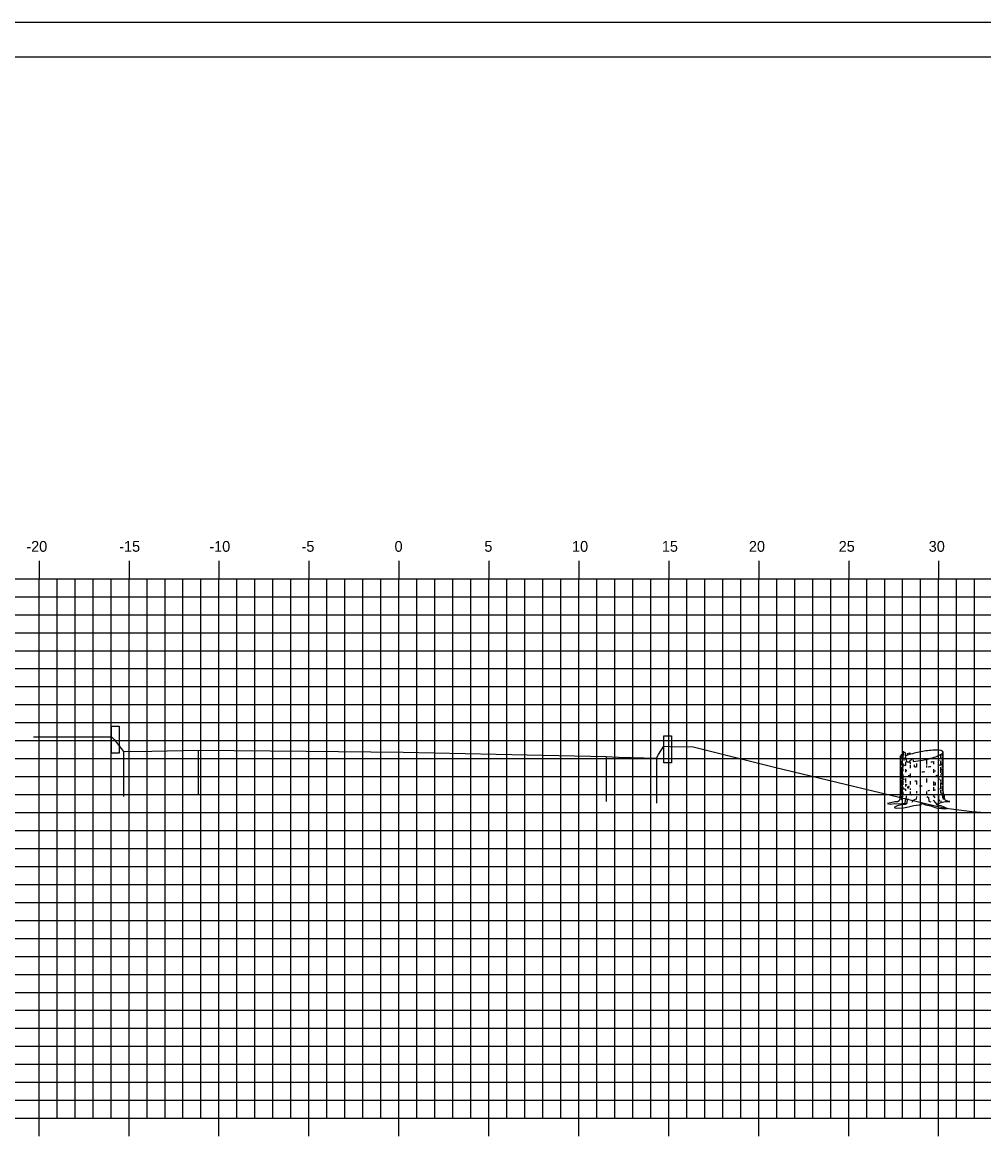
# Model space of a CAD drawing. Extents: x 1037709 to 1037879, y 394883 to 394993.
# Drawn here: x 1037771.2 to 1037824.7, y 394930.4 to 394992.6 of the extents above; entities that cross this region are included whole.
import ezdxf

# ---------------------------------------------------------------- set-up
doc = ezdxf.new("R2010")
doc.units = 0
for name, color, linetype in [('BORDER', 7, 'Continuous'), ('H_V ANNOTATION', 7, 'Continuous'), ('MAJOR', 7, 'Continuous'), ('MINOR', 7, 'Continuous'), ('PLOT BOUNDARY', 7, 'Continuous'), ('S_Curb_Type_1', 7, 'Continuous'), ('S_Roadway_Centerline', 7, 'Continuous'), ('S_Roadway_Edge_Pavement', 7, 'Continuous'), ('S_Roadway_Edge_TW', 7, 'Continuous'), ('S_Trees_Decid_Pay', 7, 'Continuous')]:
    doc.layers.add(name, color=color, linetype=linetype)

msp = doc.modelspace()

# ---------------------------------------------------------------- linework, layer by layer
at = {"layer": 'BORDER'}
msp.add_line((1037877.157, 394990.686), (1037717.157, 394990.686), dxfattribs=at)
at = {"layer": 'MAJOR'}
for p, q in [((1037772.157, 394962.688), (1037772.157, 394961.686)), ((1037777.157, 394962.688), (1037777.157, 394961.686)), ((1037782.157, 394962.688), (1037782.157, 394961.686)), ((1037787.157, 394962.688), (1037787.157, 394961.686)), ((1037792.157, 394962.688), (1037792.157, 394961.686)), ((1037797.157, 394962.688), (1037797.157, 394961.686)), ((1037802.157, 394962.688), (1037802.157, 394961.686)), ((1037807.157, 394962.688), (1037807.157, 394961.686)), ((1037812.157, 394962.688), (1037812.157, 394961.686)), ((1037817.157, 394962.688), (1037817.157, 394961.686)), ((1037822.157, 394962.688), (1037822.157, 394961.686)), ((1037722.157, 394961.686), (1037862.157, 394961.686)), ((1037772.157, 394931.686), (1037772.157, 394961.686)), ((1037777.157, 394931.686), (1037777.157, 394961.686)), ((1037782.157, 394931.686), (1037782.157, 394961.686)), ((1037787.157, 394931.686), (1037787.157, 394961.686)), ((1037792.157, 394931.686), (1037792.157, 394961.686)), ((1037797.157, 394931.686), (1037797.157, 394961.686)), ((1037802.157, 394931.686), (1037802.157, 394961.686)), ((1037807.157, 394931.686), (1037807.157, 394961.686)), ((1037812.157, 394931.686), (1037812.157, 394961.686)), ((1037817.157, 394931.686), (1037817.157, 394961.686)), ((1037822.157, 394931.686), (1037822.157, 394961.686)), ((1037722.157, 394956.686), (1037862.157, 394956.686)), ((1037722.157, 394951.686), (1037862.157, 394951.686)), ((1037722.157, 394946.686), (1037862.157, 394946.686)), ((1037722.157, 394941.686), (1037862.157, 394941.686)), ((1037722.157, 394936.686), (1037862.157, 394936.686)), ((1037722.157, 394931.686), (1037862.157, 394931.686)), ((1037772.157, 394930.684), (1037772.157, 394931.686)), ((1037777.157, 394930.684), (1037777.157, 394931.686)), ((1037782.157, 394930.684), (1037782.157, 394931.686)), ((1037787.157, 394930.684), (1037787.157, 394931.686)), ((1037792.157, 394930.684), (1037792.157, 394931.686)), ((1037797.157, 394930.684), (1037797.157, 394931.686)), ((1037802.157, 394930.684), (1037802.157, 394931.686)), ((1037807.157, 394930.684), (1037807.157, 394931.686)), ((1037812.157, 394930.684), (1037812.157, 394931.686)), ((1037817.157, 394930.684), (1037817.157, 394931.686)), ((1037822.157, 394930.684), (1037822.157, 394931.686))]:
    msp.add_line(p, q, dxfattribs=at)
at = {"layer": 'MINOR'}
for p, q in [((1037773.157, 394931.686), (1037773.157, 394961.686)), ((1037774.157, 394931.686), (1037774.157, 394961.686)), ((1037775.157, 394931.686), (1037775.157, 394961.686)), ((1037776.157, 394931.686), (1037776.157, 394961.686)), ((1037778.157, 394931.686), (1037778.157, 394961.686)), ((1037779.157, 394931.686), (1037779.157, 394961.686)), ((1037780.157, 394931.686), (1037780.157, 394961.686)), ((1037781.157, 394931.686), (1037781.157, 394961.686)), ((1037783.157, 394931.686), (1037783.157, 394961.686)), ((1037784.157, 394931.686), (1037784.157, 394961.686)), ((1037785.157, 394931.686), (1037785.157, 394961.686)), ((1037786.157, 394931.686), (1037786.157, 394961.686)), ((1037788.157, 394931.686), (1037788.157, 394961.686)), ((1037789.157, 394931.686), (1037789.157, 394961.686)), ((1037790.157, 394931.686), (1037790.157, 394961.686)), ((1037791.157, 394931.686), (1037791.157, 394961.686)), ((1037793.157, 394931.686), (1037793.157, 394961.686)), ((1037794.157, 394931.686), (1037794.157, 394961.686)), ((1037795.157, 394931.686), (1037795.157, 394961.686)), ((1037796.157, 394931.686), (1037796.157, 394961.686)), ((1037798.157, 394931.686), (1037798.157, 394961.686)), ((1037799.157, 394931.686), (1037799.157, 394961.686)), ((1037800.157, 394931.686), (1037800.157, 394961.686)), ((1037801.157, 394931.686), (1037801.157, 394961.686)), ((1037803.157, 394931.686), (1037803.157, 394961.686)), ((1037804.157, 394931.686), (1037804.157, 394961.686)), ((1037805.157, 394931.686), (1037805.157, 394961.686)), ((1037806.157, 394931.686), (1037806.157, 394961.686)), ((1037808.157, 394931.686), (1037808.157, 394961.686)), ((1037809.157, 394931.686), (1037809.157, 394961.686)), ((1037810.157, 394931.686), (1037810.157, 394961.686)), ((1037811.157, 394931.686), (1037811.157, 394961.686)), ((1037813.157, 394931.686), (1037813.157, 394961.686)), ((1037814.157, 394931.686), (1037814.157, 394961.686)), ((1037815.157, 394931.686), (1037815.157, 394961.686)), ((1037816.157, 394931.686), (1037816.157, 394961.686)), ((1037818.157, 394931.686), (1037818.157, 394961.686)), ((1037819.157, 394931.686), (1037819.157, 394961.686)), ((1037820.157, 394931.686), (1037820.157, 394961.686)), ((1037821.157, 394931.686), (1037821.157, 394961.686)), ((1037823.157, 394931.686), (1037823.157, 394961.686)), ((1037824.157, 394931.686), (1037824.157, 394961.686)), ((1037722.157, 394960.686), (1037862.157, 394960.686)), ((1037722.157, 394959.686), (1037862.157, 394959.686)), ((1037722.157, 394958.686), (1037862.157, 394958.686)), ((1037722.157, 394957.686), (1037862.157, 394957.686)), ((1037722.157, 394955.686), (1037862.157, 394955.686)), ((1037722.157, 394954.686), (1037862.157, 394954.686)), ((1037722.157, 394953.686), (1037862.157, 394953.686)), ((1037722.157, 394952.686), (1037862.157, 394952.686)), ((1037722.157, 394950.686), (1037862.157, 394950.686)), ((1037722.157, 394949.686), (1037862.157, 394949.686)), ((1037722.157, 394948.686), (1037862.157, 394948.686)), ((1037722.157, 394947.686), (1037862.157, 394947.686)), ((1037722.157, 394945.686), (1037862.157, 394945.686)), ((1037722.157, 394944.686), (1037862.157, 394944.686)), ((1037722.157, 394943.686), (1037862.157, 394943.686)), ((1037722.157, 394942.686), (1037862.157, 394942.686)), ((1037722.157, 394940.686), (1037862.157, 394940.686)), ((1037722.157, 394939.686), (1037862.157, 394939.686)), ((1037722.157, 394938.686), (1037862.157, 394938.686)), ((1037722.157, 394937.686), (1037862.157, 394937.686)), ((1037722.157, 394935.686), (1037862.157, 394935.686)), ((1037722.157, 394934.686), (1037862.157, 394934.686)), ((1037722.157, 394933.686), (1037862.157, 394933.686)), ((1037722.157, 394932.686), (1037862.157, 394932.686))]:
    msp.add_line(p, q, dxfattribs=at)
at = {"layer": 'PLOT BOUNDARY'}
msp.add_lwpolyline([(1037709.064, 394882.627), (1037879.064, 394882.627), (1037879.064, 394992.627), (1037709.064, 394992.627)], close=True, dxfattribs=at)
at = {"layer": 'S_Curb_Type_1'}
for points in [[(1037776.192, 394953.485), (1037776.609, 394953.485), (1037776.609, 394951.985), (1037776.192, 394951.985)], [(1037806.888, 394952.955), (1037807.305, 394952.955), (1037807.305, 394951.455), (1037806.888, 394951.455)]]:
    msp.add_lwpolyline(points, close=True, dxfattribs=at)
at = {"layer": 'S_Roadway_Centerline'}
msp.add_lwpolyline([(1037771.849, 394952.886), (1037775.824, 394952.902), (1037776.192, 394952.901), (1037776.324, 394952.74), (1037776.847, 394952.073), (1037778.418, 394952.103), (1037781.003, 394952.16), (1037787.002, 394952.107), (1037792.388, 394952.045), (1037799.294, 394951.888), (1037803.67, 394951.792), (1037804.367, 394951.772), (1037806.469, 394951.708), (1037806.582, 394951.908), (1037806.888, 394952.371), (1037807.229, 394952.365), (1037808.512, 394952.34), (1037813.029, 394951.214), (1037822.429, 394948.94), (1037824.001, 394948.742), (1037825.028, 394948.664)], dxfattribs=at)
at = {"layer": 'S_Roadway_Edge_Pavement'}
for p, q in [((1037776.847, 394952.073), (1037776.847, 394949.573)), ((1037806.469, 394951.708), (1037806.469, 394949.208))]:
    msp.add_line(p, q, dxfattribs=at)
at = {"layer": 'S_Roadway_Edge_TW'}
for p, q in [((1037781.003, 394952.16), (1037781.003, 394949.66)), ((1037803.67, 394951.792), (1037803.67, 394949.292))]:
    msp.add_line(p, q, dxfattribs=at)
at = {"layer": 'S_Trees_Decid_Pay'}
for p, q in [((1037820.075, 394951.552), (1037820.075, 394951.297)), ((1037820.225, 394951.752), (1037820.225, 394951.577)), ((1037820.309, 394951.503), (1037820.309, 394951.298)), ((1037820.57, 394951.505), (1037820.57, 394951.386)), ((1037821.481, 394951.643), (1037821.481, 394951.363)), ((1037821.864, 394951.744), (1037821.864, 394951.657)), ((1037821.864, 394951.516), (1037821.864, 394951.377)), ((1037822.137, 394951.657), (1037822.137, 394951.466)), ((1037822.269, 394951.911), (1037822.269, 394951.657)), ((1037822.269, 394951.561), (1037822.269, 394951.297)), ((1037822.349, 394951.955), (1037822.349, 394951.835)), ((1037822.349, 394951.783), (1037822.349, 394951.569)), ((1037822.349, 394951.524), (1037822.349, 394951.186)), ((1037820.075, 394951.2), (1037820.075, 394950.731)), ((1037820.161, 394951.406), (1037820.161, 394951.194)), ((1037820.161, 394951.129), (1037820.161, 394950.98)), ((1037820.309, 394951.091), (1037820.309, 394950.937)), ((1037820.57, 394951.334), (1037820.57, 394951.149)), ((1037820.57, 394950.863), (1037820.57, 394950.634)), ((1037820.809, 394951.233), (1037820.814, 394951.34)), ((1037820.935, 394951.406), (1037820.935, 394951.226)), ((1037821.481, 394951.297), (1037821.481, 394951.194)), ((1037821.864, 394951.091), (1037821.864, 394950.9)), ((1037822.137, 394951.214), (1037822.137, 394950.937)), ((1037822.137, 394950.892), (1037822.137, 394950.783)), ((1037822.269, 394951.2), (1037822.269, 394950.892)), ((1037822.349, 394951.069), (1037822.349, 394950.708)), ((1037820.075, 394950.68), (1037820.075, 394950.546)), ((1037820.075, 394950.488), (1037820.075, 394950.163)), ((1037820.161, 394950.803), (1037820.161, 394950.503)), ((1037820.161, 394950.465), (1037820.161, 394950.222)), ((1037820.309, 394950.574), (1037820.309, 394950.354)), ((1037820.309, 394950.254), (1037820.309, 394950.134)), ((1037820.57, 394950.436), (1037820.57, 394950.251)), ((1037820.935, 394950.448), (1037820.935, 394950.251)), ((1037821.481, 394950.583), (1037821.481, 394950.362)), ((1037821.864, 394950.42), (1037821.864, 394950.212)), ((1037822.137, 394950.648), (1037822.137, 394950.42)), ((1037822.269, 394950.803), (1037822.269, 394950.737)), ((1037822.269, 394950.503), (1037822.269, 394950.405)), ((1037822.269, 394950.354), (1037822.269, 394949.994)), ((1037822.349, 394950.671), (1037822.349, 394950.222)), ((1037820.078, 394949.611), (1037820.064, 394949.493)), ((1037820.075, 394950.134), (1037820.075, 394949.714)), ((1037820.161, 394950.111), (1037820.161, 394949.971)), ((1037820.161, 394949.839), (1037820.161, 394949.683)), ((1037820.309, 394949.983), (1037820.309, 394949.884)), ((1037820.57, 394950.016), (1037820.57, 394949.94)), ((1037820.57, 394949.862), (1037820.57, 394949.689)), ((1037820.935, 394949.868), (1037820.935, 394949.765)), ((1037821.481, 394949.862), (1037821.481, 394949.689)), ((1037821.86, 394949.634), (1037821.94, 394949.502)), ((1037821.864, 394950.09), (1037821.864, 394949.891)), ((1037822.137, 394950.09), (1037822.137, 394949.707)), ((1037822.269, 394949.942), (1037822.269, 394949.775)), ((1037822.349, 394950.157), (1037822.349, 394949.875))]:
    msp.add_line(p, q, dxfattribs=at)
for points in [[(1037820.381, 394951.499), (1037820.373, 394951.643), (1037820.328, 394951.635), (1037820.313, 394952.01), (1037820.219, 394952.018), (1037820.204, 394952.098), (1037820.167, 394951.76), (1037820.122, 394951.855), (1037820.101, 394951.701), (1037820.024, 394951.826), (1037820.03, 394951.636)], [(1037820.024, 394951.826), (1037820.024, 394949.689), (1037820.004, 394949.547), (1037819.998, 394949.421), (1037819.955, 394949.335), (1037819.862, 394949.285), (1037819.727, 394949.285), (1037819.483, 394949.23), (1037819.316, 394949.18), (1037819.459, 394949.15), (1037819.696, 394949.187), (1037819.906, 394949.174), (1037820.167, 394949.18), (1037820.291, 394949.199), (1037820.321, 394949.156), (1037820.383, 394949.199), (1037820.284, 394949.131), (1037820.049, 394949.106), (1037819.819, 394949.045), (1037819.689, 394948.974), (1037819.788, 394948.931), (1037820.21, 394948.95), (1037820.488, 394948.993), (1037820.787, 394949.069), (1037821.073, 394949.106), (1037821.178, 394949.106), (1037821.196, 394949.187), (1037821.265, 394949.193), (1037821.431, 394949.106), (1037821.717, 394949.05), (1037822.016, 394948.943), (1037822.475, 394948.894), (1037822.629, 394948.907), (1037822.288, 394949.057), (1037822.084, 394949.088), (1037822.096, 394949.162), (1037822.356, 394949.261), (1037822.531, 394949.292), (1037822.772, 394949.304), (1037822.574, 394949.341), (1037822.512, 394949.378), (1037822.488, 394949.464), (1037822.475, 394949.634), (1037822.43, 394949.72), (1037822.402, 394949.961), (1037822.402, 394952.046)], [(1037820.024, 394951.826), (1037820.07, 394951.849), (1037820.093, 394951.915), (1037820.145, 394951.938), (1037820.178, 394951.863)], [(1037820.403, 394951.865), (1037820.424, 394951.972), (1037820.556, 394952.003), (1037820.563, 394951.915)], [(1037820.542, 394951.503), (1037820.579, 394951.606), (1037820.645, 394951.612), (1037820.645, 394951.694), (1037820.719, 394951.701), (1037820.744, 394951.52)], [(1037821.978, 394950.226), (1037821.977, 394950.302), (1037821.969, 394950.369)], [(1037820.145, 394949.619), (1037820.138, 394949.493), (1037820.056, 394949.399)], [(1037820.291, 394949.199), (1037820.309, 394949.378), (1037820.371, 394949.514), (1037820.364, 394949.615)], [(1037820.433, 394950.134), (1037820.424, 394950.06), (1037820.498, 394950.054), (1037820.513, 394950.171)], [(1037822.154, 394949.648), (1037822.154, 394949.442), (1037822.211, 394949.333), (1037822.309, 394949.316)], [(1037822.294, 394949.722), (1037822.366, 394949.619), (1037822.366, 394949.493)], [(1037822.351, 394949.802), (1037822.412, 394949.642), (1037822.425, 394949.516), (1037822.417, 394949.419)], [(1037820.482, 394949.446), (1037820.408, 394949.378), (1037820.389, 394949.279), (1037820.383, 394949.199)], [(1037820.933, 394949.582), (1037820.916, 394949.428), (1037820.719, 394949.347), (1037820.673, 394949.244)], [(1037821.499, 394949.573), (1037821.602, 394949.522), (1037821.616, 394949.316), (1037821.719, 394949.287)], [(1037822.084, 394949.088), (1037821.998, 394949.23), (1037821.866, 394949.372)]]:
    msp.add_lwpolyline(points, dxfattribs=at)
for centre, radius, start, end in [((1037822.314, 394946.045), 6.126, 93.69441, 100.77788), ((1037822.003, 394950.861), 1.299, 78.27788, 93.69441), ((1037822.17, 394951.664), 0.48, 69.98432, 78.27788), ((1037822.278, 394951.961), 0.164, 55.77788, 69.98432), ((1037822.31, 394952.007), 0.107, 45.9547, 55.77788), ((1037820.834, 394950.639), 1.299, 107.86134, 113.3069), ((1037820.423, 394952.797), 1.299, 268.12894, 273.69441), ((1037822.314, 394946.045), 6.126, 100.77788, 107.86134), ((1037820.112, 394957.614), 6.126, 273.69441, 274.02462), ((1037820.112, 394957.614), 6.126, 275.91473, 280.77788), ((1037820.112, 394957.614), 6.126, 280.77788, 287.86134), ((1037821.214, 394957.397), 5.916, 274.95145, 276.30875), ((1037821.593, 394953.02), 1.299, 287.86134, 303.27788), ((1037821.79, 394952.809), 1.292, 285.56513, 289.09156), ((1037822.042, 394952.334), 0.48, 303.27788, 311.57144), ((1037822.262, 394951.79), 0.166, 301.67004, 315), ((1037822.252, 394952.098), 0.164, 311.57144, 325.77788), ((1037822.303, 394951.749), 0.109, 315, 324.82628), ((1037822.34, 394952.038), 0.0645, 33.27788, 45.9547), ((1037822.299, 394952.066), 0.107, 325.77788, 335.60106), ((1037822.338, 394951.724), 0.0657, 324.82628, 337.5), ((1037822.348, 394952.044), 0.0544, 22.46002, 33.27788), ((1037822.338, 394952.049), 0.0645, 335.60106, 348.27788), ((1037822.355, 394952.047), 0.0467, 10.77788, 22.46002), ((1037822.348, 394951.72), 0.0554, 337.5, 348.31854), ((1037822.355, 394952.047), 0.0467, 359.09574, 10.77788), ((1037822.347, 394952.047), 0.0544, 348.27788, 359.09574), ((1037820.072, 394951.458), 0.0476, 180, 191.68146), ((1037820.072, 394950.937), 0.0476, 180, 191.68146), ((1037820.08, 394951.459), 0.0554, 191.68146, 202.5), ((1037820.08, 394950.938), 0.0554, 191.68146, 202.5), ((1037820.089, 394951.463), 0.0657, 202.5, 215.17372), ((1037820.089, 394950.942), 0.0657, 202.5, 215.17372), ((1037820.125, 394951.488), 0.109, 215.17372, 225), ((1037820.125, 394950.967), 0.109, 215.17372, 225), ((1037820.166, 394951.529), 0.166, 225, 239.19244), ((1037820.166, 394951.008), 0.166, 225, 239.19244), ((1037820.166, 394951.265), 0.166, 237.03779, 239.19244), ((1037820.328, 394951.538), 0.484, 239.19244, 247.5), ((1037820.328, 394951.281), 0.484, 239.19244, 245.77245), ((1037820.637, 394952.284), 1.292, 247.5, 248.35373), ((1037820.637, 394952.548), 1.292, 250.61187, 255.28558), ((1037820.637, 394952.284), 1.292, 255.28558, 259.26323), ((1037821.213, 394957.136), 5.916, 266.07764, 267.30434), ((1037821.213, 394956.872), 5.916, 270.1162, 271.77083), ((1037821.213, 394957.136), 5.916, 273.53821, 274.89239), ((1037821.213, 394956.872), 5.916, 276.31835, 277.15463), ((1037821.789, 394952.284), 1.292, 277.15463, 278.36619), ((1037821.789, 394952.548), 1.292, 288.08294, 292.5), ((1037821.789, 394952.284), 1.292, 291.8071, 292.5), ((1037822.098, 394951.538), 0.484, 292.5, 300.80756), ((1037822.098, 394951.281), 0.484, 294.63721, 300.80756), ((1037822.098, 394951.802), 0.484, 297.41617, 300.80756), ((1037822.261, 394951.529), 0.166, 300.80756, 315), ((1037822.261, 394951.265), 0.166, 300.80756, 301.6001), ((1037822.261, 394951.008), 0.166, 300.80756, 315), ((1037822.302, 394951.488), 0.109, 315, 324.82628), ((1037822.302, 394950.967), 0.109, 315, 324.82628), ((1037822.337, 394951.463), 0.0657, 324.82628, 337.5), ((1037822.337, 394950.942), 0.0657, 324.82628, 337.5), ((1037822.347, 394951.459), 0.0554, 337.5, 348.31854), ((1037822.347, 394950.938), 0.0554, 337.5, 348.31854), ((1037820.072, 394950.679), 0.0476, 180, 191.68146), ((1037820.072, 394950.414), 0.0476, 180, 191.68146), ((1037820.08, 394950.681), 0.0554, 191.68146, 202.5), ((1037820.08, 394950.415), 0.0554, 191.68146, 202.5), ((1037820.089, 394950.685), 0.0657, 202.5, 215.17372), ((1037820.089, 394950.419), 0.0657, 202.5, 215.17372), ((1037820.125, 394950.71), 0.109, 215.17372, 225), ((1037820.125, 394950.444), 0.109, 215.17372, 225), ((1037820.166, 394950.75), 0.166, 225, 239.19244), ((1037820.166, 394950.485), 0.166, 225, 239.19244), ((1037820.328, 394950.758), 0.484, 239.19244, 247.5), ((1037820.637, 394952.027), 1.292, 247.5, 248.48417), ((1037820.637, 394951.77), 1.292, 247.5, 251.79898), ((1037820.637, 394951.504), 1.292, 247.5, 248.35373), ((1037820.637, 394951.504), 1.292, 255.28558, 259.24628), ((1037820.637, 394952.027), 1.292, 261.87258, 262.84538), ((1037821.213, 394956.615), 5.916, 262.84537, 263.7595), ((1037821.213, 394956.358), 5.916, 266.27211, 267.30434), ((1037821.789, 394951.504), 1.292, 277.15463, 278.37952), ((1037821.789, 394952.027), 1.292, 279.25654, 285.6105), ((1037821.789, 394951.77), 1.292, 285.61049, 290.10015), ((1037822.098, 394950.758), 0.484, 292.5, 300.80756), ((1037822.261, 394950.485), 0.166, 300.80756, 302.06939), ((1037822.261, 394950.75), 0.166, 302.06939, 315), ((1037822.302, 394950.71), 0.109, 315, 324.82628), ((1037822.337, 394950.685), 0.0657, 324.82628, 337.5), ((1037822.347, 394950.681), 0.0554, 337.5, 348.31854), ((1037822.347, 394950.415), 0.0554, 337.5, 348.31854), ((1037820.072, 394949.885), 0.0476, 180, 191.68146), ((1037820.08, 394949.886), 0.0554, 191.68146, 202.5), ((1037820.089, 394949.89), 0.0657, 202.5, 215.17372), ((1037820.125, 394949.915), 0.109, 215.17372, 225), ((1037820.166, 394949.956), 0.166, 225, 239.19244), ((1037820.328, 394950.229), 0.484, 239.19244, 247.5), ((1037820.328, 394950.486), 0.484, 242.73401, 247.5), ((1037820.637, 394950.975), 1.292, 247.5, 248.35373), ((1037820.637, 394951.232), 1.292, 251.36642, 255.28558), ((1037821.213, 394955.563), 5.916, 263.78314, 264.76555), ((1037821.213, 394956.092), 5.916, 268.92065, 270), ((1037821.213, 394956.092), 5.916, 270, 270.27568), ((1037821.213, 394955.82), 5.916, 273.26366, 274.46102), ((1037821.213, 394956.092), 5.916, 276.31835, 277.15463), ((1037821.213, 394955.82), 5.916, 276.31835, 277.15463), ((1037821.789, 394951.232), 1.292, 277.15463, 278.36619), ((1037821.789, 394951.232), 1.292, 285.61049, 289.15336), ((1037821.798, 394950.979), 1.292, 291.36963, 292.0604), ((1037822.098, 394950.229), 0.484, 292.5, 296.54992), ((1037822.261, 394950.213), 0.166, 302.06939, 315), ((1037822.302, 394950.172), 0.109, 315, 324.82628), ((1037822.337, 394950.147), 0.0657, 324.82628, 337.5), ((1037822.347, 394950.144), 0.0554, 337.5, 348.31854)]:
    msp.add_arc(centre, radius, start, end, dxfattribs=at)

# ---------------------------------------------------------------- texts
at = {"layer": 'H_V ANNOTATION'}
for s, p in [('-20', (1037771.45, 394963.186)), ('-15', (1037776.614, 394963.186)), ('-10', (1037781.622, 394963.186)), ('-5', (1037786.747, 394963.186)), ('0', (1037791.916, 394963.186)), ('5', (1037796.908, 394963.186)), ('10', (1037801.782, 394963.186)), ('15', (1037806.774, 394963.186)), ('20', (1037811.611, 394963.186)), ('25', (1037816.603, 394963.186)), ('30', (1037821.606, 394963.186))]:
    msp.add_text(s, height=0.6, dxfattribs=at).set_placement(p)
at = {"layer": 'S_Roadway_Centerline'}
for s, p in [('C', (1037792.383, 394952.045)), ('L', (1037792.388, 394952.038))]:
    msp.add_text(s, height=0.0146, dxfattribs=at).set_placement(p)

doc.saveas('drawing.dxf')
